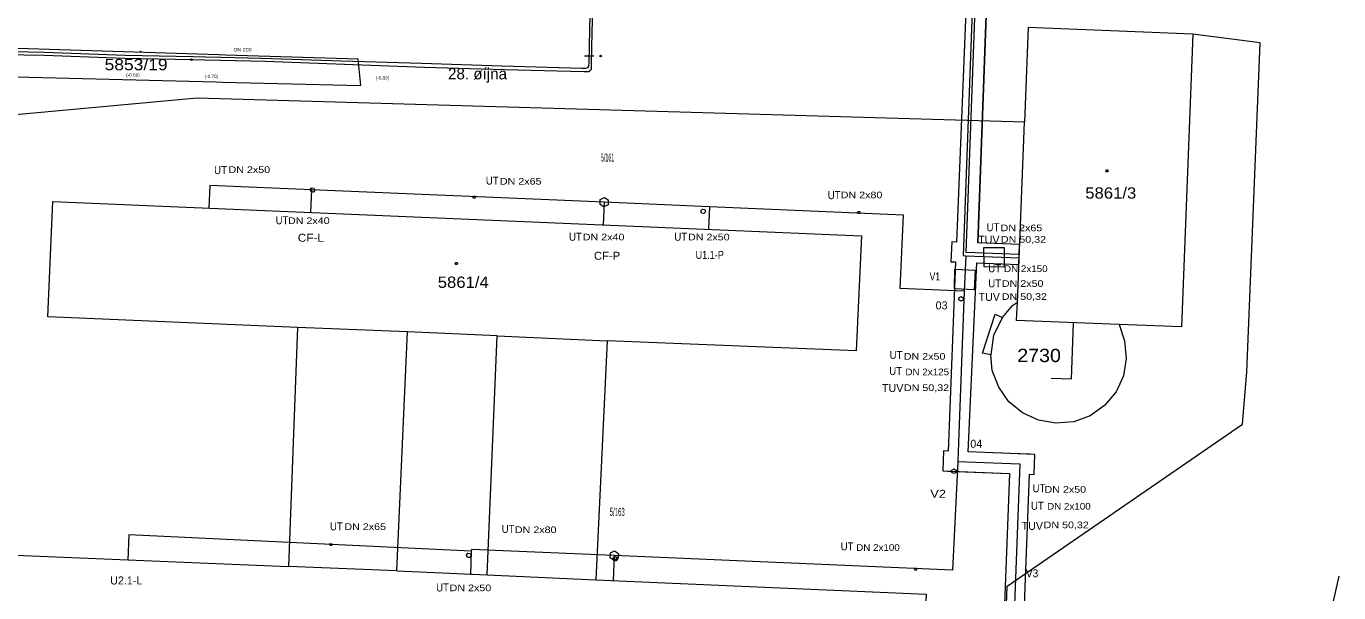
# Model space of a CAD drawing. Extents: x -725191 to -724881, y -978080 to -977718.
# Drawn here: x -725081.4 to -724884.7, y -977926.4 to -977841.3 of the extents above; entities that cross this region are included whole.
import ezdxf
from ezdxf.enums import TextEntityAlignment as Align

# ---------------------------------------------------------------- set-up
doc = ezdxf.new("R2010")
doc.units = 0
doc.header["$LTSCALE"] = 0.48
doc.header["$PDMODE"] = 32
doc.header["$PDSIZE"] = 0.24
for name, color, linetype, lineweight in [('1', 7, 'Continuous', 13), ('4', 7, 'Continuous', 13), ('46', 7, 'Continuous', 13), ('48', 7, 'Continuous', 13), ('5', 7, 'Continuous', 13), ('63', 7, 'Continuous', 13), ('7', 7, 'Continuous', 13)]:
    doc.layers.add(name, color=color, linetype=linetype, lineweight=lineweight)
doc.layers.add('2', color=7, linetype='Continuous')

msp = doc.modelspace()

# ---------------------------------------------------------------- linework, layer by layer
at = {"layer": '1'}
for p, q in [((-725031.28, -977850.26), (-725031.66, -977846.24)), ((-725055.84, -977852.15), (-725090.85, -977855.37)), ((-724931.78, -977855.72), (-725055.84, -977852.15)), ((-725077.44, -977867.64), (-724956.22, -977872.8)), ((-724956.22, -977872.8), (-724957.03, -977890.04)), ((-725040.76, -977886.55), (-725042.12, -977922.44)), ((-724994.35, -977888.55), (-724996.03, -977924.46)), ((-724957.03, -977890.04), (-724994.35, -977888.55)), ((-724934.4, -977925.39), (-724899.12, -977901.08)), ((-724884.666, -977923.907), (-724895, -977969)), ((-724938.86, -978049.3), (-724934.4, -977925.39))]:
    msp.add_line(p, q, dxfattribs=at)
for points in [[(-724899.12, -977901.08), (-724898.44, -977893.24), (-724896.45, -977843.83), (-724906.56, -977842.55), (-724931.22, -977841.52), (-724931.78, -977855.72)], [(-725105.06, -977843.95), (-725052.58, -977845.59), (-725051.57, -977845.62), (-725031.66, -977846.24)], [(-724906.56, -977842.55), (-724908.26, -977886.48), (-724917.59, -977886.11), (-724916.78, -977888.56), (-724916.53, -977891.2), (-724916.96, -977893.81), (-724918.04, -977896.23), (-724919.78, -977898.25)], [(-725105.09, -977848.39), (-725053.02, -977849.71), (-725052.02, -977849.73), (-725031.28, -977850.26)], [(-724934.14, -977897.7), (-724935.65, -977895.52), (-724936.61, -977893.01), (-724936.81, -977890.66), (-724938.07, -977890.42), (-724936.19, -977884.57), (-724935.07, -977885.07), (-724933.57, -977883.28), (-724932.85, -977882.74), (-724931.78, -977855.72)], [(-725040.76, -977886.55), (-725078.21, -977884.98), (-725077.44, -977867.64)], [(-724919.78, -977898.25), (-724921.93, -977899.81), (-724924.39, -977900.71), (-724927.06, -977900.92), (-724929.7, -977900.46), (-724932.1, -977899.38), (-724934.14, -977897.7)], [(-725035.36, -977935.22), (-725043.75, -977934.93), (-725044.06, -977940.9), (-725092.45, -977938.91), (-725091.57, -977920.38), (-725042.12, -977922.44)], [(-724996.03, -977924.46), (-724946.52, -977926.6), (-724947.3, -977944.91), (-724995.66, -977942.85)]]:
    msp.add_lwpolyline(points, dxfattribs=at)
at = {"layer": '4'}
for p, q in [((-725024.31, -977887.21), (-725040.76, -977886.55)), ((-725025.89, -977923.1), (-725024.31, -977887.21)), ((-725010.86, -977887.82), (-725024.31, -977887.21)), ((-725010.86, -977887.82), (-724994.35, -977888.55)), ((-725025.89, -977923.1), (-725042.12, -977922.44)), ((-725012.33, -977923.68), (-724996.03, -977924.46))]:
    msp.add_line(p, q, dxfattribs=at)
for points in [[(-724917.59, -977886.11), (-724932.96, -977885.5), (-724932.85, -977882.74)], [(-724935.07, -977885.07), (-724936.44, -977887.71), (-724936.81, -977890.66)], [(-725025.89, -977923.1), (-725012.33, -977923.68), (-725010.86, -977887.82)]]:
    msp.add_lwpolyline(points, dxfattribs=at)
at = {"layer": '46'}
for points in [[(-725014.19, -977866.859), (-725014.109, -977867.014), (-725014.206, -977867.159), (-725014.386, -977867.149), (-725014.468, -977866.994), (-725014.37, -977866.849)], [(-724956.521, -977869.16), (-724956.44, -977869.314), (-724956.537, -977869.459), (-724956.717, -977869.45), (-724956.799, -977869.295), (-724956.701, -977869.15)], [(-725035.663, -977919.007), (-725035.581, -977919.161), (-725035.679, -977919.306), (-725035.859, -977919.297), (-725035.94, -977919.142), (-725035.843, -977918.997)], [(-724948.006, -977922.67), (-724947.923, -977922.824), (-724948.02, -977922.97), (-724948.2, -977922.961), (-724948.283, -977922.807), (-724948.186, -977922.662)]]:
    msp.add_lwpolyline(points, close=True, dxfattribs=at)
at = {"layer": '48'}
msp.add_line((-724997.756, -977845.785), (-724996.334, -977845.801), dxfattribs=at)
msp.add_lwpolyline([(-724995.343, -977845.85), (-724995.365, -977845.812), (-724995.342, -977845.775), (-724995.297, -977845.775), (-724995.275, -977845.813), (-724995.298, -977845.85)], close=True, dxfattribs=at)
msp.add_point((-724995.32, -977845.812), dxfattribs=at)
at = {"layer": '5'}
for points in [[(-724919.31, -977862.88), (-724919.22, -977863.03), (-724919.31, -977863.18), (-724919.49, -977863.18), (-724919.58, -977863.03), (-724919.49, -977862.88)], [(-725016.86, -977876.79), (-725016.77, -977876.94), (-725016.86, -977877.09), (-725017.04, -977877.09), (-725017.13, -977876.94), (-725017.04, -977876.79)]]:
    msp.add_lwpolyline(points, close=True, dxfattribs=at)
at = {"layer": '63'}
for p, q in [((-724939.222, -977838.756), (-724940.562, -977875.291)), ((-724932.568, -977875.608), (-724940.562, -977875.291)), ((-724940.582, -977875.791), (-724932.588, -977876.107))]:
    msp.add_line(p, q, dxfattribs=at)
for points in [[(-724946.744, -977810.509), (-724949.211, -977812.215), (-724940.029, -977825.495), (-724942.001, -977873.733), (-724942.701, -977873.705), (-724942.819, -977876.703), (-724942.12, -977876.73), (-724943.226, -977905.12), (-724943.926, -977905.093), (-724944.039, -977908.091), (-724934.046, -977908.468), (-724936.266, -977967.326), (-724933.268, -977967.439), (-724931.048, -977908.581), (-724930.349, -977908.607), (-724930.236, -977905.61), (-724940.229, -977905.233), (-724938.908, -977876.858), (-724932.627, -977877.107), (-724932.509, -977874.109), (-724938.79, -977873.86), (-724936.993, -977824.611)], [(-724946.744, -977810.509), (-724949.211, -977812.215), (-724940.029, -977825.495), (-724942.001, -977873.733), (-724942.701, -977873.705), (-724942.819, -977876.703), (-724942.12, -977876.73), (-724943.226, -977905.12), (-724943.926, -977905.093), (-724944.039, -977908.091), (-724934.046, -977908.468), (-724936.266, -977967.326), (-724933.268, -977967.439), (-724931.048, -977908.581), (-724930.349, -977908.607), (-724930.236, -977905.61), (-724940.229, -977905.233), (-724938.908, -977876.858), (-724932.627, -977877.107), (-724932.509, -977874.109), (-724938.79, -977873.86), (-724936.993, -977824.611)], [(-724946.744, -977810.509), (-724949.211, -977812.215), (-724940.029, -977825.495), (-724942.001, -977873.733), (-724942.701, -977873.705), (-724942.819, -977876.703), (-724942.12, -977876.73), (-724943.226, -977905.12), (-724943.926, -977905.093), (-724944.039, -977908.091), (-724934.046, -977908.468), (-724936.266, -977967.326), (-724933.268, -977967.439), (-724931.048, -977908.581), (-724930.349, -977908.607), (-724930.236, -977905.61), (-724940.229, -977905.233), (-724938.908, -977876.858), (-724932.627, -977877.107), (-724932.509, -977874.109), (-724938.79, -977873.86), (-724936.993, -977824.611)], [(-725064.314, -977845.166), (-725064.335, -977845.128), (-725064.312, -977845.091), (-725064.267, -977845.092), (-725064.245, -977845.13), (-725064.269, -977845.167)], [(-725064.321, -977846.829), (-725064.299, -977846.867), (-725064.322, -977846.904), (-725064.367, -977846.903), (-725064.389, -977846.865), (-725064.366, -977846.828)], [(-725038.739, -977866.209), (-725038.89, -977865.894), (-725038.683, -977865.612), (-725038.324, -977865.646), (-725038.173, -977865.962), (-725038.381, -977866.243)], [(-724995.385, -977867.367), (-724994.768, -977867.035), (-724994.186, -977867.423), (-724994.22, -977868.142), (-724994.836, -977868.474), (-724995.418, -977868.086)], [(-724980.058, -977868.786), (-724979.714, -977868.85), (-724979.608, -977869.183), (-724979.846, -977869.453), (-724980.19, -977869.39), (-724980.296, -977869.056)], [(-724934.85, -977877.5), (-724937.85, -977877.46), (-724937.86, -977874.56), (-724934.83, -977874.55)], [(-724939.31, -977880.91), (-724942.28, -977880.78), (-724942.22, -977877.83), (-724939.2, -977877.96)], [(-724941.262, -977881.923), (-724940.968, -977882.113), (-724940.998, -977882.462), (-724941.321, -977882.62), (-724941.615, -977882.43), (-724941.585, -977882.082)], [(-724942.342, -977907.795), (-724942.048, -977907.985), (-724942.078, -977908.334), (-724942.401, -977908.492), (-724942.695, -977908.302), (-724942.665, -977907.954)], [(-725015.228, -977920.446), (-725014.88, -977920.477), (-725014.743, -977920.799), (-725014.955, -977921.09), (-725015.303, -977921.059), (-725015.44, -977920.737)], [(-724993.869, -977920.403), (-724993.253, -977920.072), (-724992.67, -977920.459), (-724992.704, -977921.179), (-724993.32, -977921.51), (-724993.903, -977921.122)], [(-724993.343, -977920.991), (-724992.993, -977920.983), (-724992.822, -977921.288), (-724993, -977921.601), (-724993.35, -977921.608), (-724993.521, -977921.303)]]:
    msp.add_lwpolyline(points, close=True, dxfattribs=at)
for points in [[(-724946.744, -977810.509), (-724949.211, -977812.215), (-724940.029, -977825.495), (-724942.001, -977873.733), (-724942.701, -977873.705), (-724942.819, -977876.703), (-724942.12, -977876.73), (-724943.226, -977905.12), (-724943.926, -977905.093), (-724944.039, -977908.091), (-724943.34, -977908.117), (-724934.046, -977908.468), (-724936.266, -977967.326), (-724933.268, -977967.439), (-724931.048, -977908.581), (-724930.349, -977908.607), (-724930.236, -977905.61), (-724930.935, -977905.583), (-724933.933, -977905.47)], [(-724946.744, -977810.509), (-724936.993, -977824.611), (-724938.79, -977873.86)], [(-724996.78, -977832.3), (-724997.07, -977844.29), (-724997.12, -977846.74), (-724997.13, -977847.34), (-724997.28, -977847.6), (-724997.53, -977847.71), (-724998.14, -977847.69), (-725010.12, -977847.35), (-725022.19, -977846.94), (-725034.17, -977846.58), (-725046.16, -977846.17), (-725052.297, -977846.041), (-725054.5, -977845.99), (-725056.407, -977845.955), (-725066.64, -977845.74), (-725078.71, -977845.31), (-725090.71, -977845.05), (-725102.48, -977844.75), (-725114.72, -977844.37)], [(-725114.7, -977844.66), (-725102.42, -977845.11), (-725090.73, -977845.48), (-725078.78, -977845.7), (-725066.72, -977846.15), (-725056.681, -977846.35), (-725054.7, -977846.39), (-725052.296, -977846.437), (-725045.64, -977846.57), (-725033.74, -977847.05), (-725021.75, -977847.47), (-725009.76, -977847.84), (-724997.78, -977848.14), (-724997.15, -977848.14), (-724996.88, -977847.98), (-724996.72, -977847.77), (-724996.68, -977847.12), (-724996.65, -977844.4), (-724996.35, -977832.44)], [(-724939.636, -977839.037), (-724940.981, -977875.775), (-724940.582, -977875.791), (-724940.821, -977881.133), (-724941.626, -977902.478), (-724941.784, -977906.675), (-724932.491, -977907.026), (-724934.684, -977965.184)], [(-725038.662, -977865.888), (-725053.949, -977865.237), (-725054.093, -977868.634)], [(-724994.802, -977867.755), (-725038.662, -977865.888), (-725038.807, -977869.285)], [(-724979.016, -977868.427), (-724994.802, -977867.755), (-724994.947, -977871.152)], [(-724940.821, -977881.133), (-724950.411, -977880.704), (-724949.919, -977869.715), (-724979.016, -977868.427), (-724979.167, -977871.823)], [(-724933.933, -977905.47), (-724940.229, -977905.233), (-724938.908, -977876.858), (-724932.627, -977877.107), (-724932.509, -977874.109), (-724938.79, -977873.86)], [(-724924.467, -977885.837), (-724924.804, -977894.33), (-724927.801, -977894.211)], [(-724941.784, -977906.675), (-724942.561, -977922.966), (-724993.287, -977920.791), (-724993.449, -977924.587)], [(-725014.724, -977920.126), (-725066.07, -977917.67), (-725066.232, -977921.466)], [(-724993.287, -977920.791), (-725014.717, -977919.872), (-725014.724, -977920.126), (-725014.83, -977923.671)]]:
    msp.add_lwpolyline(points, dxfattribs=at)
msp.add_point((-725056.681, -977846.35), dxfattribs=at)

# ---------------------------------------------------------------- texts
at = {"layer": '2'}
for s, width, p in [('5853/19', 1.15, (-725069.703, -977847.95)), ('5861/3', 1.1, (-724922.673, -977867.22)), ('5861/4', 1.1, (-725019.753, -977880.61))]:
    msp.add_text(s, height=1.7, dxfattribs=dict(at, width=width)).set_placement(p)
at = {"layer": '46'}
for s, p in [('(-0.60)', (-725065.4505, -977848.907)), ('(-0.70)', (-725053.6995, -977849.116)), ('(-0.80)', (-725028.0635, -977849.343))]:
    msp.add_text(s, height=0.5, dxfattribs=at).set_placement(p, align=Align.CENTER)
at = {"layer": '63'}
for s, height, width, p in [('DN 200', 0.5, 1.2, (-725049.017, -977845.11)), ('DN 2x50', 1, 1.2, (-725048.002, -977863.372)), ('DN 2x65', 1, 1.2, (-725007.3175, -977865.118)), ('DN 2x80', 1, 1.2, (-724956.2125, -977867.166)), ('DN 2x40', 1, 1.2, (-725039.0825, -977871.027)), ('DN 2x65', 1, 1.2, (-724932.2435, -977872.111)), ('DN 2x40', 1, 1.2, (-724994.885, -977873.49)), ('DN 2x50', 1, 1.2, (-724979.1095, -977873.49)), ('DN 50,32', 1, 1.2, (-724931.93, -977873.841)), ('DN 2x150', 1, 1.1, (-724931.585, -977878.24)), ('DN 2x50', 1, 1.2, (-724932.0555, -977880.458)), ('DN 50,32', 1, 1.2, (-724931.8045, -977882.414)), ('DN 2x50', 1, 1.2, (-724946.7605, -977891.395)), ('DN 2x125', 1, 1.1, (-724946.361, -977893.725)), ('DN 50,32', 1, 1.2, (-724946.4685, -977896.1)), ('DN 2x50', 1, 1.2, (-724925.66, -977911.364)), ('DN 2x100', 1, 1.1, (-724925.1275, -977913.893)), ('DN 2x65', 1, 1.2, (-725030.6295, -977916.955)), ('DN 2x80', 1, 1.2, (-725005.069, -977917.421)), ('DN 50,32', 1, 1.2, (-724925.527, -977916.689)), ('DN 2x100', 1, 1.1, (-724953.749, -977920.083)), ('DN 2x50', 1, 1.2, (-725014.8535, -977926.141))]:
    msp.add_text(s, height=height, dxfattribs=dict(at, width=width)).set_placement(p, align=Align.CENTER)
at = {"layer": '7'}
msp.add_text('28. øíjna', height=1.7, dxfattribs=at).set_placement((-725018.213, -977849.32))
for s, height, width, p in [('5/161', 1.2, 0.4, (-724994.283, -977861.658)), ('UT', 1.2, 0.9, (-725052.3125, -977863.538)), ('UT', 1.2, 0.9, (-725011.5795, -977865.118)), ('UT', 1.2, 0.9, (-724960.3175, -977867.298)), ('UT', 1.2, 0.9, (-725043.1005, -977871.058)), ('UT', 1.2, 0.9, (-724936.5045, -977872.111)), ('CF-L', 1.2, 1.1, (-725038.7795, -977873.694)), ('UT', 1.2, 0.9, (-724999.1085, -977873.54)), ('UT', 1.2, 0.9, (-724983.3165, -977873.54)), ('CF-P', 1.2, 1.05, (-724994.3645, -977876.394)), ('U1.1-P', 1.2, 0.85, (-724978.9745, -977876.259)), ('UT', 1.2, 0.9, (-724936.2535, -977878.278)), ('V1', 1.2, 0.8, (-724945.224, -977879.499)), ('UT', 1.2, 0.9, (-724936.2535, -977880.534)), ('UT', 1.2, 0.9, (-724951.0435, -977891.287)), ('2730', 2, 1.1, (-724929.5945, -977891.755)), ('UT', 1.2, 0.9, (-724951.1055, -977893.694)), ('V2 ', 1.2, 1.2, (-724944.463, -977912.118)), ('UT', 1.2, 0.9, (-724929.6115, -977911.29)), ('UT', 1.2, 0.9, (-724929.8615, -977913.922)), ('5/163', 1.2, 0.45, (-724992.842, -977914.825)), ('UT', 1.2, 0.9, (-725034.9535, -977917.006)), ('UT', 1.2, 0.9, (-725009.1975, -977917.382)), ('UT', 1.2, 0.9, (-724958.3755, -977920.014)), ('V3', 1.2, 0.95, (-724930.6445, -977924.049)), ('UT', 1.2, 0.9, (-725019.0365, -977926.18))]:
    msp.add_text(s, height=height, dxfattribs=dict(at, width=width)).set_placement(p, align=Align.CENTER)
for s, p in [('TUV', (-724937.131, -977873.991)), ('TUV', (-724937.0685, -977882.564)), ('03', (-724944.2125, -977883.842)), ('TUV', (-724951.5445, -977896.25)), ('04', (-724939.0145, -977904.609)), ('TUV', (-724930.614, -977916.93)), ('U2.1-L', (-725066.4545, -977925.129))]:
    msp.add_text(s, height=1.2, dxfattribs=at).set_placement(p, align=Align.CENTER)

doc.saveas('drawing.dxf')
